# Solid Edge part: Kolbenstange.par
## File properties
Username: bmolnar
Dokumentum tartalom típus: 0
Author: bmolnar
Last saved by: bmolnar
Revision: 90
Sűrűség: 0,000 kg/m^3
Pontosság: 0,990
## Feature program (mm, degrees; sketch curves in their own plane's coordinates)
base feature "unnamed BaseFeature 1"
sketch for "unnamed Protrusion 1" plane through (61.5, 0, 0) normal (1, 0, 0) x-axis (0, 0, 1)
  circle centre (0, 0) radius 40
extrude "unnamed Protrusion 1" add finite 19.5 along +normal
sketch for "Kihúzás_2" plane through (61.5, 0, 0) normal (1, 0, 0) x-axis (0, 0, 1)
  circle centre (0, 0) radius 40
extrude "Kihúzás_2" add finite 4.5 along -normal
thread "unnamed Thread 1"
chamfer "Letörés_1" setback 3.3  SetBackValue2 = 20 deg
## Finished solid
Body 1: solid body, 17 faces, 23 edges, 8 vertices.
  Faces by surface: plane 8, cylinder 4, torus 3, cone 2
  Edges by curve: circle 13, line 6, ellipse 2, intersection 2
Bounding box of the edges (mm; curved faces can reach further): 156.000 x 80.000 x 80.000, from (-75, -40, -40) to (81, 40, 40).
Cylindrical faces by radius (mm): R6.75 x1, R8 x1, R10 x1, R40 x1
Conical faces (half-angle, radius in mm at the cone's reference point): 20 deg R6.7989 x1, 60 deg R7.475 x1
Toroidal faces (ring radius, tube radius in mm): R7.15 r0.4 x2, R8.2 r1.8 x1
Planar faces by outward normal: +x 1, +y 1, -x 3, -y 1, oblique 2
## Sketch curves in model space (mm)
circle centre (61.5, 0, 0) radius 40
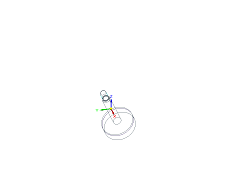
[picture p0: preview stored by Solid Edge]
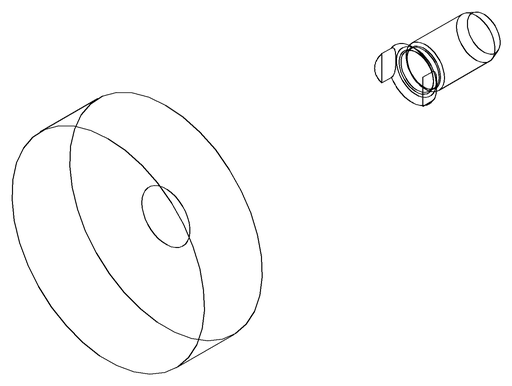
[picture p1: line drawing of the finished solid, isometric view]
